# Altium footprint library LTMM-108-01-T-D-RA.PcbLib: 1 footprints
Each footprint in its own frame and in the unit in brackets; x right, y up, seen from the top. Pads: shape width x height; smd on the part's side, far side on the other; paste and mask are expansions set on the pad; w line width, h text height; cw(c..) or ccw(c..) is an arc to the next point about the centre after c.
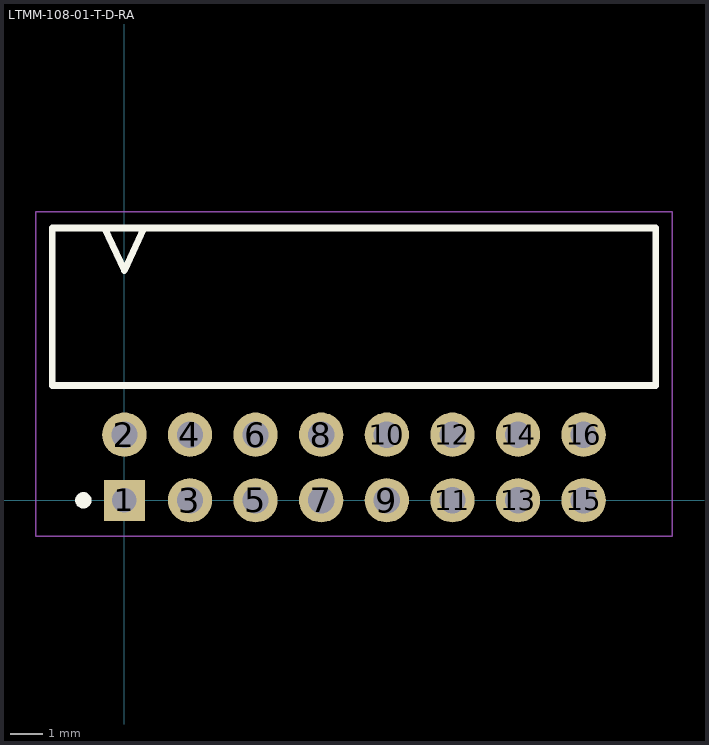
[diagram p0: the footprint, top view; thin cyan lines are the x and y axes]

## LTMM-108-01-T-D-RA [mm] "2.00mm pitch, 16 pin, header; shrouded, r/a, PTH"
height 6.6
pads (16):
  rect 1.25x1.25 / inner round 1.25 / far side rect 1.25x1.25 hole 0.75 mask+0: 1(0,0)
  round 1.35 hole 0.8 mask+0: 2(0,2) 3(2,0) 4(2,2) 5(4,0) 6(4,2) 7(6,0) 8(6,2) 9(8,0) 10(8,2) 11(10,0) 12(10,2) 13(12,0) 14(12,2) 15(14,0) 16(14,2)
Top Overlay:
  circle w0.25: c-1.25,0 r0.125
  lines w0.2: -0.6,8.3 0,7 0.6,8.3 ; -2.2,3.5 16.2,3.5 16.2,8.3 -2.2,8.3 -2.2,3.5
Mechanical 12:
  lines w0.001: -2.2,3.5 16.2,3.5 16.2,8.3 -2.2,8.3 -2.2,3.5
Mechanical 13:
  circle w0.1: c-1.25,0 r0.125
  lines w0.1: -0.6,8.3 0,7 0.6,8.3 ; -2.2,3.5 16.2,3.5 16.2,8.3 -2.2,8.3 -2.2,3.5
  text ".Designator" at 0.254,0.254 h1.52
Mechanical 15:
  lines w0.05: -2.7,-1.1 16.7,-1.1 16.7,8.8 -2.7,8.8 -2.7,-1.1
